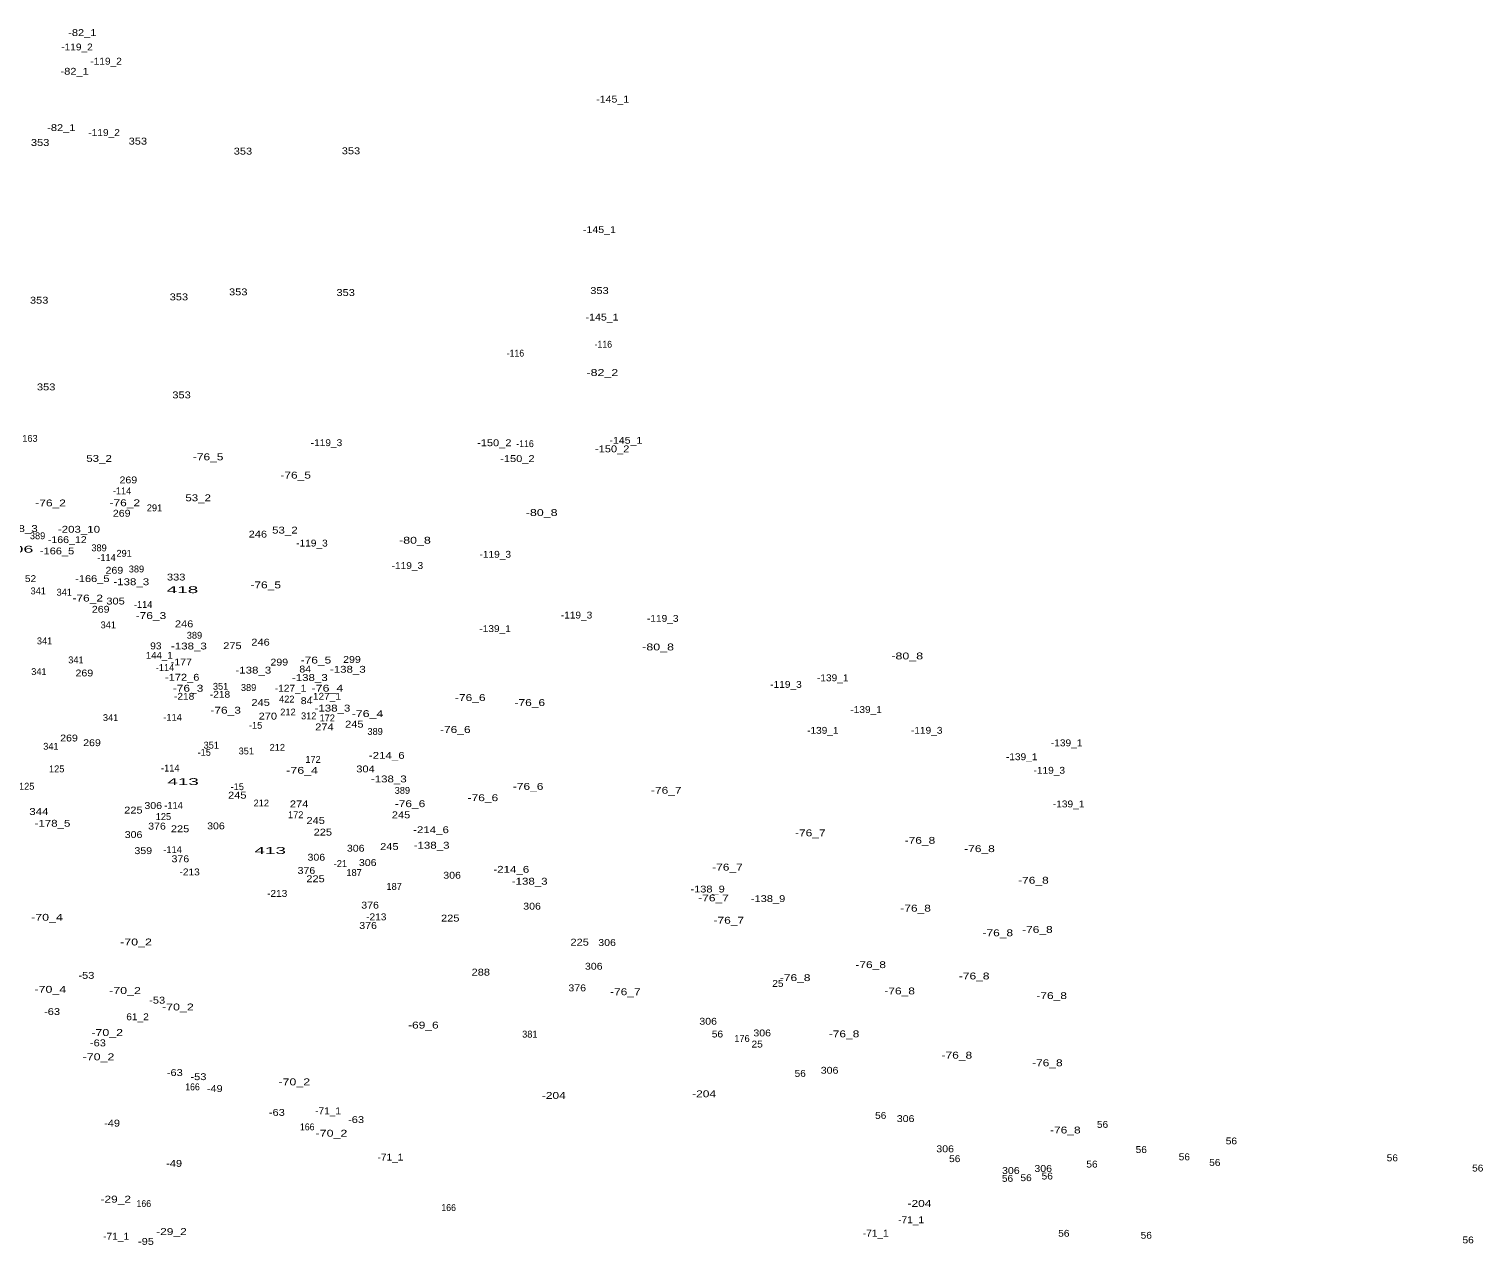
# Model space of a CAD drawing. Extents: x -658110 to -655750, y -1000429 to -997657.
# Drawn here: x -656702 to -655857, y -999114 to -998407 of the extents above; entities that cross this region are included whole.
import ezdxf
from ezdxf.enums import TextEntityAlignment as Align

# ---------------------------------------------------------------- set-up
doc = ezdxf.new("R2010")
doc.units = 0
doc.header["$LTSCALE"] = 1.6
doc.layers.add('24', color=7, linetype='Continuous')

msp = doc.modelspace()

# ---------------------------------------------------------------- texts
at = {"layer": '24'}
for s, width, p in [('-82_1', 1.2, (-656670.62, -998410.82)), ('-119_2', 1.1, (-656673.701, -998419.18)), ('-82_1', 1.2, (-656675.079, -998433.32)), ('-119_2', 1.1, (-656656.801, -998427.44)), ('-145_1', 1.15, (-656362.36, -998449.53)), ('-82_1', 1.2, (-656682.829, -998466.09)), ('-119_2', 1.1, (-656657.961, -998468.93)), ('353', 1.2, (-656695.14, -998474.73)), ('353', 1.2, (-656638.34, -998473.95)), ('353', 1.2, (-656577.26, -998479.77)), ('353', 1.2, (-656514.459, -998479.59)), ('-145_1', 1.15, (-656370.04, -998525.4)), ('353', 1.2, (-656579.98, -998561.62)), ('353', 1.2, (-656517.549, -998562.01)), ('353', 1.2, (-656370.03, -998560.85)), ('353', 1.2, (-656695.72, -998566.46)), ('353', 1.2, (-656614.49, -998564.52)), ('-145_1', 1.15, (-656368.5, -998576.3)), ('-116', 0.95, (-656367.79, -998592.08)), ('-116', 0.95, (-656418.87, -998597.26)), ('-82_2', 1.35, (-656368.34, -998608.53)), ('353', 1.2, (-656691.64, -998616.89)), ('353', 1.2, (-656612.929, -998621.54)), ('-119_3', 1.1, (-656528.701, -998649.32)), ('-150_2', 1.2, (-656431.169, -998649.36)), ('-116', 0.95, (-656413.3, -998649.89)), ('-150_2', 1.2, (-656362.63, -998652.91)), ('-145_1', 1.15, (-656354.669, -998647.94)), ('53_2', 1.25, (-656660.87, -998658.48)), ('-76_5', 1.3, (-656597.481, -998657.55)), ('-150_2', 1.2, (-656417.73, -998658.58)), ('269', 1.15, (-656643.86, -998670.98)), ('-76_5', 1.3, (-656546.62, -998668.19)), ('-76_2', 1.3, (-656689.061, -998684.38)), ('-76_2', 1.3, (-656645.931, -998684.28)), ('53_2', 1.25, (-656603.29, -998681.36)), ('269', 1.15, (-656647.73, -998690.36)), ('-80_8', 1.35, (-656403.61, -998689.97)), ('-138_3', 1.25, (-656706.959, -998699.28)), ('-203_10', 1.25, (-656672.57, -998699.69)), ('246', 1.2, (-656568.59, -998702.51)), ('53_2', 1.25, (-656552.88, -998700.17)), ('106', 1.95, (-656707.759, -998711.27)), ('-166_5', 1.2, (-656685.31, -998712.29)), ('-166_12', 1.15, (-656679.36, -998705.72)), ('-119_3', 1.1, (-656537.15, -998707.72)), ('-80_8', 1.35, (-656477.28, -998706.07)), ('-119_3', 1.1, (-656481.66, -998720.77)), ('-119_3', 1.1, (-656430.591, -998714.24)), ('52', 1.1, (-656700.72, -998728.39)), ('-166_5', 1.2, (-656664.81, -998728.38)), ('269', 1.15, (-656651.99, -998723.53)), ('-138_3', 1.25, (-656642.16, -998730.21)), ('333', 1.2, (-656616.059, -998727.47)), ('418', 2.05, (-656612.393, -998734.8)), ('-76_5', 1.3, (-656564.03, -998732.03)), ('-76_2', 1.3, (-656667.49, -998739.7)), ('269', 1.15, (-656659.94, -998746.22)), ('305', 1.2, (-656651.299, -998741.44)), ('-76_3', 1.3, (-656630.731, -998749.86)), ('246', 1.2, (-656611.44, -998754.68)), ('-119_3', 1.1, (-656383.361, -998749.59)), ('-119_3', 1.1, (-656333.24, -998751.5)), ('-139_1', 1.1, (-656430.691, -998757.46)), ('144_1', 1.05, (-656625.89, -998772.98)), ('93', 1.1, (-656627.88, -998767.5)), ('-138_3', 1.25, (-656608.669, -998767.58)), ('275', 1.2, (-656583.37, -998767.39)), ('246', 1.2, (-656567.04, -998765.34)), ('-80_8', 1.35, (-656335.949, -998768.13)), ('-177', 1.15, (-656613.059, -998776.89)), ('-138_3', 1.25, (-656571.22, -998781.6)), ('299', 1.15, (-656556.14, -998776.95)), ('84', 1.15, (-656541.049, -998780.96)), ('-76_5', 1.3, (-656534.821, -998775.76)), ('-138_3', 1.25, (-656516.299, -998781.12)), ('299', 1.15, (-656513.88, -998775.4)), ('-80_8', 1.35, (-656191.14, -998773.37)), ('269', 1.15, (-656669.44, -998783.27)), ('-172_6', 1.2, (-656612.57, -998785.75)), ('-138_3', 1.25, (-656538.39, -998785.92)), ('-119_3', 1.1, (-656261.62, -998789.91)), ('-139_1', 1.1, (-656234.431, -998786.07)), ('-76_3', 1.3, (-656609.16, -998792.14)), ('-218', 1.1, (-656611.421, -998796.83)), ('-218', 1.1, (-656590.581, -998795.68)), ('-127_1', 1.1, (-656549.571, -998792.11)), ('-127_1', 1.1, (-656529.41, -998796.81)), ('-76_4', 1.35, (-656528.15, -998792.11)), ('-76_6', 1.3, (-656445.14, -998797.57)), ('-76_3', 1.3, (-656587.311, -998804.91)), ('245', 1.2, (-656566.98, -998800.42)), ('84', 1.15, (-656540.25, -998799.37)), ('-138_3', 1.25, (-656525.23, -998803.69)), ('-76_4', 1.35, (-656504.851, -998806.9)), ('-76_6', 1.3, (-656410.52, -998800.47)), ('-139_1', 1.1, (-656215.041, -998804.5)), ('270', 1.2, (-656562.79, -998808.36)), ('274', 1.2, (-656529.88, -998814.62)), ('245', 1.2, (-656512.51, -998813.02)), ('269', 1.15, (-656678.36, -998821.09)), ('269', 1.15, (-656664.98, -998823.81)), ('-76_6', 1.3, (-656453.84, -998816.14)), ('-139_1', 1.1, (-656240.201, -998816.62)), ('-119_3', 1.1, (-656179.821, -998816.61)), ('-139_1', 1.1, (-656098.49, -998823.9)), ('-214_6', 1.25, (-656493.67, -998831.19)), ('-139_1', 1.1, (-656124.611, -998831.97)), ('-76_4', 1.35, (-656542.851, -998839.89)), ('304', 1.2, (-656506.01, -998839.07)), ('-119_3', 1.1, (-656108.581, -998839.86)), ('413', 2.05, (-656612.053, -998846.44)), ('-138_3', 1.25, (-656492.49, -998844.89)), ('-76_6', 1.3, (-656411.49, -998849.22)), ('245', 1.2, (-656580.549, -998854.33)), ('-76_6', 1.3, (-656437.79, -998855.8)), ('-76_7', 1.3, (-656331.209, -998851.49)), ('344', 1.25, (-656695.88, -998863.86)), ('225', 1.2, (-656640.929, -998863.01)), ('306', 1.15, (-656629.39, -998860.36)), ('274', 1.2, (-656544.61, -998859.42)), ('245', 1.2, (-656485.36, -998865.77)), ('-76_6', 1.3, (-656480.14, -998859.28)), ('-139_1', 1.1, (-656097.341, -998859.43)), ('-178_5', 1.25, (-656687.96, -998870.68)), ('376', 1.15, (-656627.21, -998872.33)), ('225', 1.2, (-656613.79, -998873.87)), ('306', 1.15, (-656592.941, -998872.19)), ('245', 1.2, (-656534.99, -998869.07)), ('-214_6', 1.25, (-656467.94, -998874.41)), ('306', 1.15, (-656640.831, -998877.24)), ('225', 1.2, (-656530.819, -998875.81)), ('-76_7', 1.3, (-656247.47, -998876.25)), ('-76_8', 1.3, (-656183.75, -998880.61)), ('359', 1.15, (-656635.19, -998886.6)), ('376', 1.15, (-656613.64, -998891.33)), ('413', 2.05, (-656561.403, -998886.5)), ('306', 1.15, (-656534.591, -998890.42)), ('306', 1.15, (-656511.711, -998885.18)), ('245', 1.2, (-656492.15, -998884.2)), ('-138_3', 1.25, (-656467.61, -998883.45)), ('-76_8', 1.3, (-656149.14, -998885.44)), ('-213', 1.1, (-656608.24, -998898.98)), ('376', 1.15, (-656540.36, -998898.12)), ('306', 1.15, (-656504.731, -998893.52)), ('-214_6', 1.25, (-656421.28, -998897.46)), ('-76_7', 1.3, (-656295.63, -998896.18)), ('225', 1.2, (-656535.079, -998902.96)), ('306', 1.15, (-656455.681, -998900.9)), ('-138_3', 1.25, (-656410.59, -998904.39)), ('-76_8', 1.3, (-656117.801, -998903.82)), ('-213', 1.1, (-656557.351, -998911.47)), ('-138_9', 1.2, (-656307.171, -998908.92)), ('-76_7', 1.3, (-656303.75, -998914.12)), ('-138_9', 1.2, (-656272.03, -998914.49)), ('-70_4', 1.35, (-656691.14, -998925.35)), ('376', 1.15, (-656503.34, -998918.29)), ('-213', 1.1, (-656499.75, -998925.1)), ('306', 1.15, (-656409.211, -998918.91)), ('-76_8', 1.3, (-656186.28, -998920.05)), ('376', 1.15, (-656504.5, -998930.12)), ('225', 1.2, (-656456.76, -998925.84)), ('-76_7', 1.3, (-656294.85, -998927.08)), ('-76_8', 1.3, (-656115.481, -998932.46)), ('-70_2', 1.35, (-656639.4, -998939.72)), ('225', 1.2, (-656381.54, -998939.81)), ('306', 1.15, (-656365.591, -998940.05)), ('-76_8', 1.3, (-656138.5, -998934.39)), ('-53', 1.2, (-656668.27, -998959.12)), ('288', 1.2, (-656439, -998957.25)), ('306', 1.15, (-656373.351, -998953.82)), ('-76_8', 1.3, (-656212.39, -998952.91)), ('-70_4', 1.35, (-656689.2, -998967.24)), ('376', 1.15, (-656382.95, -998966.39)), ('25', 1.1, (-656266.309, -998963.8)), ('-76_8', 1.3, (-656256.28, -998960.45)), ('-76_8', 1.3, (-656152.231, -998959.49)), ('-70_2', 1.35, (-656645.79, -998967.94)), ('-53', 1.2, (-656627.11, -998973.56)), ('-76_7', 1.3, (-656355, -998968.65)), ('-76_8', 1.3, (-656195.551, -998968.19)), ('-76_8', 1.3, (-656107.181, -998970.91)), ('-63', 1.2, (-656688.21, -998980.16)), ('61_2', 1.1, (-656638.52, -998983.21)), ('-70_2', 1.35, (-656615.06, -998977.51)), ('-70_2', 1.35, (-656656.17, -998992.37)), ('-69_6', 1.3, (-656472.39, -998988.05)), ('306', 1.15, (-656306.851, -998985.82)), ('306', 1.15, (-656275.441, -998992.61)), ('-63', 1.2, (-656661.56, -998998.4)), ('56', 1.1, (-656301.45, -998993.24)), ('25', 1.1, (-656278.38, -998999.09)), ('-76_8', 1.3, (-656227.861, -998993.16)), ('-70_2', 1.35, (-656661.21, -999006.5)), ('-76_8', 1.3, (-656162.301, -999005.54)), ('-63', 1.2, (-656616.87, -999015.64)), ('-53', 1.2, (-656603.12, -999018.05)), ('56', 1.1, (-656253.33, -999016.15)), ('306', 1.15, (-656236.27, -999014.33)), ('-76_8', 1.3, (-656109.691, -999009.99)), ('166', 0.95, (-656606.58, -999023.97)), ('-49', 1.2, (-656593.66, -999024.96)), ('-70_2', 1.35, (-656547.41, -999021.06)), ('-204', 1.3, (-656396.58, -999028.97)), ('-204', 1.3, (-656309.21, -999028.01)), ('-63', 1.2, (-656557.55, -999038.82)), ('-71_1', 1.1, (-656527.78, -999037.9)), ('-63', 1.2, (-656511.51, -999042.99)), ('56', 1.1, (-656206.56, -999040.6)), ('306', 1.15, (-656192.071, -999042.45)), ('-49', 1.2, (-656653.341, -999045.06)), ('166', 0.95, (-656539.89, -999047.24)), ('-70_2', 1.35, (-656525.8, -999050.93)), ('-76_8', 1.3, (-656099.24, -999049.07)), ('56', 1.1, (-656077.6, -999045.8)), ('306', 1.15, (-656169.091, -999060.01)), ('56', 1.1, (-656055.09, -999060.44)), ('56', 1.1, (-656002.72, -999055.42)), ('-49', 1.2, (-656617.26, -999068.47)), ('-71_1', 1.1, (-656491.541, -999064.84)), ('56', 1.1, (-656163.54, -999065.74)), ('56', 1.1, (-656083.76, -999068.91)), ('56', 1.1, (-656030.07, -999064.67)), ('56', 1.1, (-656012.36, -999067.95)), ('56', 1.1, (-655909.18, -999065.24)), ('56', 1.1, (-656132.84, -999077.19)), ('306', 1.15, (-656130.91, -999072.62)), ('56', 1.1, (-656122.07, -999076.8)), ('306', 1.15, (-656112.101, -999071.45)), ('56', 1.1, (-656109.75, -999075.84)), ('56', 1.1, (-655859.53, -999071.21)), ('-29_2', 1.3, (-656651.19, -999089.29)), ('166', 0.95, (-656634.88, -999091.85)), ('166', 0.95, (-656457.69, -999094.18)), ('-204', 1.3, (-656184.03, -999091.77)), ('-71_1', 1.1, (-656188.9, -999101.29)), ('-71_1', 1.1, (-656650.981, -999110.85)), ('-29_2', 1.3, (-656618.81, -999108.11)), ('-71_1', 1.1, (-656209.451, -999109.05)), ('56', 1.1, (-656100.11, -999109.13)), ('56', 1.1, (-656052.19, -999110.29)), ('-95', 1.2, (-656633.62, -999113.85)), ('56', 1.1, (-655865.11, -999112.99))]:
    msp.add_text(s, height=4, dxfattribs=dict(at, width=width)).set_placement(p, align=Align.CENTER)
for s, p in [('163', (-656701.071, -998646.82)), ('-114', (-656647.52, -998677.33)), ('291', (-656628.66, -998687.21)), ('389', (-656696.613, -998703.46)), ('389', (-656660.893, -998710.48)), ('291', (-656646.311, -998713.68)), ('-114', (-656656.55, -998716.13)), ('389', (-656639.153, -998722.78)), ('341', (-656696.25, -998735.53)), ('341', (-656681.12, -998736.3)), ('-114', (-656635.24, -998743.41)), ('341', (-656655.53, -998755.31)), ('341', (-656692.559, -998764.62)), ('389', (-656605.433, -998761.34)), ('341', (-656674.34, -998775.67)), ('-114', (-656622.56, -998780.07)), ('341', (-656695.86, -998782.46)), ('351', (-656590.25, -998791.02)), ('389', (-656573.963, -998791.73)), ('422', (-656551.781, -998798.46)), ('212', (-656551.079, -998805.96)), ('341', (-656654.179, -998809.22)), ('-114', (-656618.15, -998809.03)), ('-15', (-656569.89, -998813.7)), ('312', (-656539.02, -998808.22)), ('172', (-656528.26, -998809.38)), ('389', (-656500.423, -998817.26)), ('341', (-656688.88, -998825.9)), ('-15', (-656599.75, -998829.41)), ('351', (-656595.66, -998825.24)), ('351', (-656575.299, -998828.63)), ('212', (-656557.28, -998826.51)), ('125', (-656685.5, -998839.04)), ('-114', (-656619.49, -998838.57)), ('172', (-656536.5, -998833.52)), ('125', (-656702.939, -998849.13)), ('-15', (-656580.551, -998849.39)), ('389', (-656484.583, -998851.54)), ('-114', (-656617.57, -998860.25)), ('212', (-656566.59, -998858.9)), ('172', (-656546.581, -998865.71)), ('125', (-656623.459, -998866.77)), ('-114', (-656618.15, -998885.99)), ('-21', (-656520.611, -998894.11)), ('187', (-656512.64, -998899.34)), ('187', (-656489.361, -998907.38)), ('381', (-656410.49, -998993.32)), ('176', (-656287.18, -998995.84))]:
    msp.add_text(s, height=4, dxfattribs=at).set_placement(p, align=Align.CENTER)

doc.saveas('drawing.dxf')
